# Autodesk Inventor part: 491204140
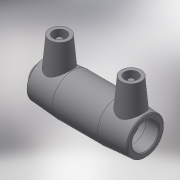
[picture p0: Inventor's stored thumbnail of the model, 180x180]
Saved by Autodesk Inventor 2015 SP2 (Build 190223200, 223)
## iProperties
Created: 2017-06
Part Number: 491204140
Material: Generic
Description: PLASSON END CAP 140
Document SubType Name: Modeling
Designer: KIM
Mass: 38.9236 g
Surface Area: 152.394 cm^2
Volume: 38.9236 cm^3
Density: 1 g/cm^3
Appearance: Default
Author: KIM
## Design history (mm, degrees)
derived "491204.ipt"
feature "Solid1::491204.ipt"
tag "TaggingFeature1"
body "Solid1"
other parameters: "d0" = 183, "d2" = 174, "d4" = 59.25, "d5" = 156.6, "d6" = 133, "d8" = 168 deg, "d10" = 36, "d11" = 12, "d13" = 189.6, "d14" = 17.6296, "d17" = 133, "d19" = 3.52592, "d20" = 168 deg, "d22" = 163.56, "d23" = 174, "d24" = 158.6532, "d25" = 135 deg, "d26" = 85.32, "d27" = 135 deg, "d29" = 97, "d30" = 15, "d31" = 75.84, "d34" = 5 deg, "d35" = 15, "d39" = 5 deg, "d41" = 4, "d42" = 14, "d43" = 0, "d45" = 4, "d46" = 14, "d47" = 0, "d48" = 237, "d49" = 1, "d51" = 112, "d52" = 4.266, "d53" = 154, "d54" = 4.266, "d56" = 14, "d57" = 4.2, "d60" = 35.55, "d61" = 2.8, "d63" = 237, "d64" = 1, "d66" = 112, "d67" = 28, "d68" = 154, "d69" = 4.74, "d70" = 0, "d71" = 4.266, "d72" = 3, "d73" = 0, "d74" = 26.1, "d75" = 8.7, "d76" = 3, "d77" = 0, "L_" = 237, "D_" = 174, "A_" = 97, "d_2" = 12, "L_0" = 183, "d55" = 14
